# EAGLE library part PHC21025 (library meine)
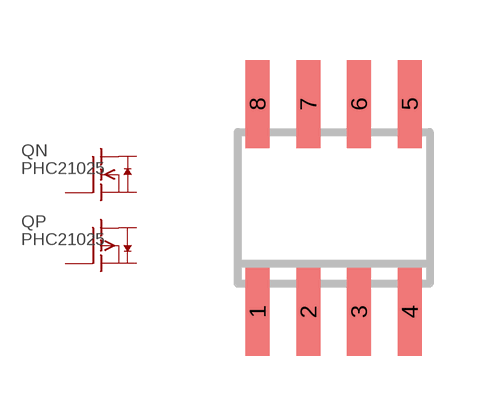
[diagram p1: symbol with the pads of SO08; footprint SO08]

Designator prefix Q; gates N=FET-EN-G2DS P=FET-EP-G2DS

## PHC21025  [SO08]
1  N:S1  pas
2  N:G1  pas
3  P:S1  pas
4  P:G1  pas
5  P:D2  pas
6  P:D3  pas
7  N:D2  pas
8  N:D3  pas

## Footprint SO08 (pad centres in mm)
smd 0.6 x 2.2: 1 -1.879,-2.64; 2 -0.609,-2.64; 3 0.661,-2.64; 4 1.931,-2.64; 5 1.931,2.56; 6 0.661,2.56; 7 -0.609,2.56; 8 -1.879,2.56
